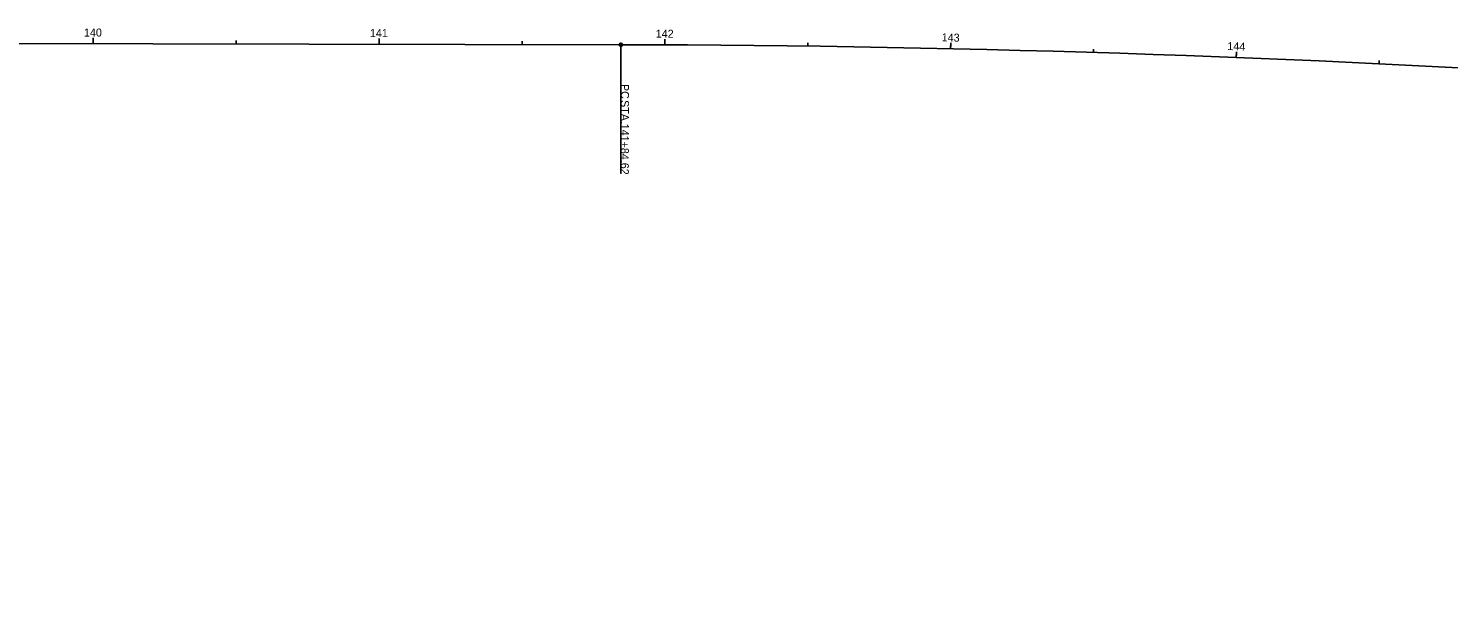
# Model space of a CAD drawing. Extents: x 1501024 to 1508874, y 327839 to 328839.
# Drawn here: x 1502004.7 to 1502501.7, y 328255.2 to 328455.9 of the extents above; entities that cross this region are included whole.
import ezdxf

# ---------------------------------------------------------------- set-up
doc = ezdxf.new("R2010")
doc.units = 0
for name, color, linetype in [('GE_X_Alignment', 7, 'Continuous'), ('GE_X_Alignment_100_Cardinal_Points', 7, 'Continuous'), ('GE_X_Alignment_100_Stations', 7, 'Continuous'), ('GE_X_Alignment_500_Cardinal_Points', 7, 'Continuous'), ('GE_X_Alignment_500_Stations', 7, 'Continuous')]:
    doc.layers.add(name, color=color, linetype=linetype)

msp = doc.modelspace()

# ---------------------------------------------------------------- linework, layer by layer
at = {"layer": 'GE_X_Alignment'}
msp.add_line((1501027.44, 328452.53), (1502212.06, 328450.23), dxfattribs=at)
msp.add_arc((1502200.96, 322720.66), 5729.58, 75.005634, 89.888968, dxfattribs=at)
at = {"layer": 'GE_X_Alignment_100_Cardinal_Points'}
msp.add_line((1502212.06, 328450.23), (1502211.97, 328405.23), dxfattribs=at)
msp.add_circle((1502212.06, 328450.23), 0.6, dxfattribs=at)
at = {"layer": 'GE_X_Alignment_100_Stations'}
for p, q in [((1502027.44, 328450.59), (1502027.44, 328452.59)), ((1502077.44, 328450.49), (1502077.44, 328451.69)), ((1502127.44, 328450.4), (1502127.44, 328452.4)), ((1502177.44, 328450.3), (1502177.44, 328451.5)), ((1502227.44, 328450.18), (1502227.45, 328452.18)), ((1502277.44, 328449.73), (1502277.45, 328450.93)), ((1502327.43, 328448.85), (1502327.47, 328450.85)), ((1502377.41, 328447.53), (1502377.45, 328448.72)), ((1502427.38, 328445.77), (1502427.46, 328447.77)), ((1502477.33, 328443.57), (1502477.39, 328444.77))]:
    msp.add_line(p, q, dxfattribs=at)
at = {"layer": 'GE_X_Alignment_500_Cardinal_Points'}
msp.add_line((1502212.06, 328450.23), (1502211.97, 328405.23), dxfattribs=at)
msp.add_circle((1502212.06, 328450.23), 0.6, dxfattribs=at)
at = {"layer": 'GE_X_Alignment_500_Stations'}
for p, q in [((1502027.44, 328450.59), (1502027.44, 328452.59)), ((1502127.44, 328450.4), (1502127.44, 328451.6)), ((1502227.44, 328450.18), (1502227.45, 328451.38)), ((1502327.43, 328448.85), (1502327.46, 328450.05)), ((1502427.38, 328445.77), (1502427.43, 328446.97))]:
    msp.add_line(p, q, dxfattribs=at)

# ---------------------------------------------------------------- texts
at = {"layer": 'GE_X_Alignment_100_Cardinal_Points'}
for s, p in [('PC', (1502212.07, 328436.51)), (' STA. ', (1502212.06, 328431.91)), ('141+84.62', (1502212.04, 328422.59))]:
    msp.add_text(s, height=2.8, rotation=269.889, dxfattribs=at).set_placement(p)
at = {"layer": 'GE_X_Alignment_100_Stations'}
for s, rotation, p in [('140', 359.889, (1502024.18, 328453.1)), ('141', 359.889, (1502124.22, 328452.9)), ('142', 359.7352, (1502224.24, 328452.7)), ('143', 358.7352, (1502324.29, 328451.42)), ('144', 357.7352, (1502424.2, 328448.39))]:
    msp.add_text(s, height=2.8, rotation=rotation, dxfattribs=at).set_placement(p)
at = {"layer": 'GE_X_Alignment_500_Cardinal_Points'}
for s, p in [('PC', (1502212.07, 328436.51)), (' STA. ', (1502212.06, 328431.91)), ('141+84.62', (1502212.04, 328422.59))]:
    msp.add_text(s, height=2.8, rotation=269.889, dxfattribs=at).set_placement(p)
at = {"layer": 'GE_X_Alignment_500_Stations'}
msp.add_text('140', height=2.8, rotation=359.889, dxfattribs=at).set_placement((1502024.18, 328453.1))

doc.saveas('drawing.dxf')
